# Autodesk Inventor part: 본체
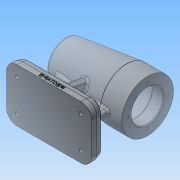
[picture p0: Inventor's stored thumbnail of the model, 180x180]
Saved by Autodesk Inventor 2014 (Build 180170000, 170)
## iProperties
Created: 2017-01
Part Number: 본체
Material: 일반
Document SubType Name: Modeling
Designer: nert
Density: 1 g/cm^3
Appearance: 기본값
Mass: 293.207 g
Surface Area: 663.375 cm^2
Volume: 293.207 cm^3
Author: nert
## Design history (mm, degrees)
sketch "스케치1"
  geometry: L1 (-56, -35)-(56, -35); L2 (56, -35)-(56, 35); L3 (56, 35)-(-56, 35); L4 (-56, 35)-(-56, -35); L5 (-56, -35)-(56, 35); L6 (56, -35)-(-56, 35); 1 further point
  constraints: 12 end point, 2 horizontal, 2 midpoint, 2 vertical
  dimensions: "d0" = 112 distance of L2.end L3.end; "d1" = 70 distance of L1.end L2.end
extrude "돌출1" new body sketch "스케치1" distance "d2" = 14; taper "d3" = 0 deg
node "작업 평면1"
sketch "스케치2"
  geometry: L1 (112, 0)-(0, 0) reference; L2 (0, 0)-(0, 14) reference; L3 (112, 14)-(0, 14) reference; L4 (112, 0)-(112, 14) reference; L5 (112, 108)-(112, 74); L6 (112, 74)-(0, 74); L7 (112, 108)-(84, 108); L8 (84, 108)-(3.73, 98.144); L9 (112, 95)-(97, 95); L10 (97, 95)-(97, 98); L11 (97, 98)-(43, 98); L12 (43, 98)-(43, 95); L13 (43, 95)-(31, 95); L14 (31, 95)-(31, 91.5); L15 (31, 91.5)-(13, 91.5); L16 (13, 91.5)-(13, 90); L17 (13, 90)-(9, 90); L18 (9, 90)-(9, 84.5); L19 (9, 84.5)-(6, 84.5); L20 (6, 84.5)-(6, 74); A1 r 80 centre (80, 74) between (3.73, 98.144) and (0, 74); 4 further points
  constraints: 32 end point, 6 parallel, 3 midpoint, 2 point on circle, 2 point on line, 2 vertical alignment, 1 centre point, 1 horizontal, 1 tangent, 1 vertical
  dimensions: "d4" = 74 distance between parallel lines of L6 L1; "d6" = 28 distance of L5.start L7.end; "d7" = 7 deg angle of L7 L8; "d8" = 80 radius of A1; "d9" = 112 distance from line of L6.end L5; "d10" = 21 diameter of L19 L6; "d11" = 32 diameter of L17 L6; "d13" = 35 diameter of L15 L6; "d14" = 42 diameter of L13 L6; "d15" = 48 diameter of L11 L6; "d16" = 42 diameter of L9 L6; "d17" = 15 distance of L9.start L9.end; "d18" = 54 distance of L10.end L11.end; "d19" = 18 distance of L14.end L15.end; "d20" = 12 distance of L12.end L13.end; "d21" = 4 distance of L16.end L17.end; "d22" = 3 distance of L18.end L19.end; "d23" = 68 diameter of L7 L6
  node "투영된 루프1"
revolve "회전1" stored, may be unused: angle "d24" = 90 deg
sketch "스케치3"
  geometry: L1 (112, 0)-(0, 0) reference; L2 (0, 0)-(0, 14) reference; L3 (112, 14)-(0, 14) reference; L4 (112, 0)-(112, 14) reference; L5 (18, 74)-(18, 10.118); L6 (18, 10.118)-(94, 10.118); L7 (94, 10.118)-(94, 74); L8 (94, 74)-(18, 74); L9 (84, 40)-(84, 108) reference; L10 (112, 40)-(112, 108) reference; 4 further points
  constraints: 8 end point, 3 midpoint, 2 horizontal, 1 horizontal alignment, 1 vertical alignment
  dimensions: "d25" = 90 deg angle of L5 L3; "d26" = 90 deg angle of L3 L7; "d27" = 18 horizontal distance of L5.end L2.end; "d28" = 18 distance from line of L4 L6.end
extrude "돌출2" join sketch "스케치3" stored distance "d29" = 8; taper "d30" = 0 deg
node "작업 평면2"
sketch "스케치4"
  geometry: L1 (70, 0)-(0, 0) reference; L2 (0, 0)-(0, 14) reference; L3 (70, 14)-(0, 14) reference; L4 (70, 0)-(70, 14) reference; L5 (12, 14)-(22.58, 74); L6 (22.58, 74)-(47.42, 74); L7 (47.42, 74)-(58, 14); L8 (58, 14)-(12, 14); C1 r 34 at (35, 74) reference; 4 further points
  constraints: 8 end point, 3 midpoint, 1 coincident, 1 horizontal, 1 horizontal alignment, 1 vertical alignment
  dimensions: "d31" = 100 deg angle of L5 L3; "d32" = 100 deg angle of L3 L7; "d33" = 12 distance from line of L5.start L2; "d34" = 12 distance of L3.start L7.end; "d37" = 14 distance between parallel lines of L1 L8
extrude "돌출3" join sketch "스케치4" stored distance "d38" = 8; taper "d39" = 0 deg
sketch "스케치5"
  geometry: L1 (56, 35)-(-56, 35) reference; L2 (-56, 35)-(-56, -35) reference; L3 (-39.113, -26)-(-44.887, -26); L4 (-44.887, -26)-(-47.774, -21); L5 (-47.774, -21)-(-44.887, -16); L6 (-44.887, -16)-(-39.113, -16); L7 (-39.113, -16)-(-36.226, -21); L8 (-36.226, -21)-(-39.113, -26); L9 (-39.113, 16)-(-44.887, 16); L10 (-44.887, 16)-(-47.774, 21); L11 (-47.774, 21)-(-44.887, 26); L12 (-44.887, 26)-(-39.113, 26); L13 (-39.113, 26)-(-36.226, 21); L14 (-36.226, 21)-(-39.113, 16); C1 r 5 at (-42, 21); C2 r 5 at (-42, -21); 3 further points
  constraints: 24 end point, 2 centre point, 2 coincident, 2 horizontal, 1 equal radius, 1 parallel, 1 tangent, 1 vertical alignment, 26 other
  dimensions: "d40" = 42 distance of point (-42, 21) point (-42, -21); "d41" = 10 diameter of C1; "d42" = 14 distance from line of point (-42, 21) L2; "d43" = 14 distance from line of point (-42, 21) L1
extrude "돌출4" cut sketch "스케치5" distance "d44" = 4; taper "d45" = 0 deg
sketch "스케치6"
  geometry: L1 (-56, 35)-(-56, -35) reference; L2 (-56, -35)-(56, -35) reference; C1 r 2.5 at (-42, -21); 1 further point
  constraints: 1 centre point
  dimensions: "d46" = 5 diameter of C1; "d47" = 14 distance from line of L1 C1.centre; "d48" = 14 distance from line of L2 C1.centre
extrude "돌출5" cut sketch "스케치6" stored distance "d49" = 4; taper "d50" = 0 deg
revolve "회전2" stored, may be unused: angle "d51" = 90 deg
sketch "스케치7"
  geometry: C1 r 21 at (0, 0) reference; 2 further points
  constraints: 1 horizontal alignment
  dimensions: "d52" = 26 distance of C1.centre point (-26, 0)
hole "구멍1" sketch "스케치7" at (-26, 0) diameter "d53" = 3.242; stored, may be unused: countersink angle "d57" = 90 deg, drill point angle "d59" = 118 deg; dims "d54" = 8, "d55" = 4, "d56" = 2, "d58" = 11
fillet "모깎기1" dims "d78" = 14
chamfer "모따기6" distance "d79" = 7; stored, may be unused: second distance "d80" = 2, angle "d81" = 15 deg
fillet "모깎기2" dims "d82" = 1
sketch "스케치8"
  geometry: L1 (0, 0)-(84, 0) reference; L2 (98, 0)-(98, 7) reference; 2 further points
  constraints: 1 other
  dimensions: "d83" = 4 distance from line of L1 point (42, 4); "d84" = 56 distance from line of L2 point (42, 4)
feature "엠보싱1" sketch "스케치8" dims "d85" = 0.5, "d86" = 0
fillet "모깎기3" dims "d87" = 3
fillet "모깎기4" dims "d88" = 3
fillet "모깎기5" dims "d89" = 3
fillet "모깎기6" dims "d90" = 3
chamfer "모따기7" distance "d91" = 1; stored, may be unused: second distance "d92" = 2, angle "d93" = 15 deg
fillet "모깎기7" dims "d94" = 0.3
fillet "모깎기8" dims "d95" = 3
fillet "모깎기9" dims "d96" = 3
fillet "모깎기10" dims "d97" = 3
chamfer "모따기2" distance "d66" = 7; stored, may be unused: second distance "d67" = 2, angle "d68" = 15 deg
chamfer "모따기3" distance "d69" = 7; stored, may be unused: second distance "d70" = 2, angle "d71" = 15 deg
chamfer "모따기4" distance "d72" = 7; stored, may be unused: second distance "d73" = 2, angle "d74" = 15 deg
chamfer "모따기5" distance "d75" = 7; stored, may be unused: second distance "d76" = 2, angle "d77" = 15 deg
node "솔리드1"
mirror "대칭1"
mirror "대칭2"
pattern_circular "원형 패턴1" dims angle "d61" = 360 deg
node "투영된 루프2"
node "투영된 루프3"
node "투영된 루프4"
node "투영된 루프5"
